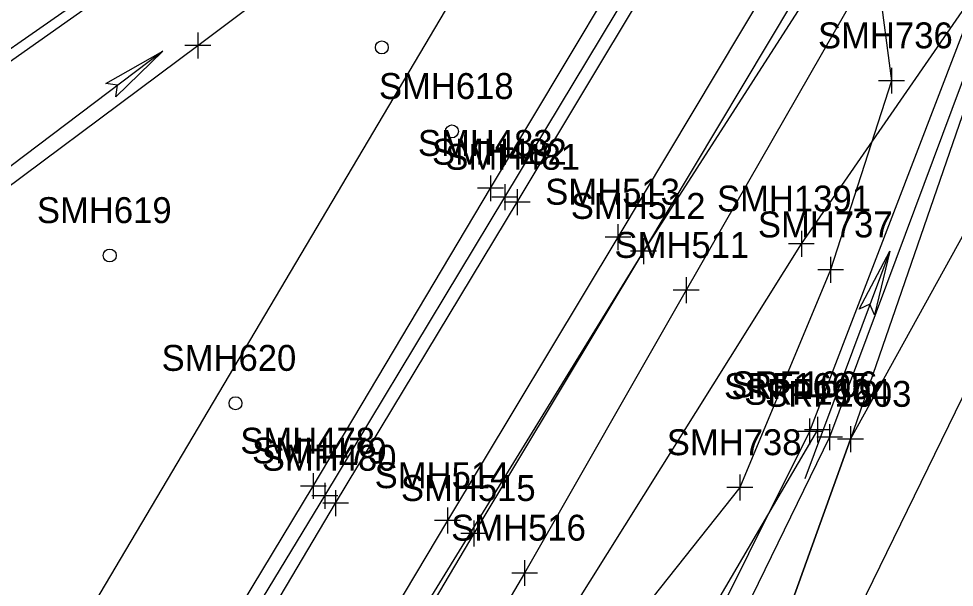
# Model space of a CAD drawing. Extents: x 941041 to 969446, y 397014 to 416764.
# Drawn here: x 952192.2 to 952336.7, y 403311.8 to 403399.5 of the extents above; entities that cross this region are included whole.
import ezdxf

# ---------------------------------------------------------------- set-up
doc = ezdxf.new("R2010")
doc.units = 0
for name, color, linetype in [('SURVEY - DRAINAGE - Area Shapes', 7, 'Continuous'), ('SURVEY - DRAINAGE - Area Shapes Text', 7, 'Continuous'), ('SURVEY - DTM - Breaklines', 7, 'Continuous'), ('SURVEY - DTM - Breaklines - Points - Locators', 7, 'Continuous'), ('SURVEY - DTM - Breaklines - Points - Numbers', 7, 'Continuous'), ('SURVEY - DTM - Spot Points - Locators', 7, 'Continuous'), ('SURVEY - DTM - Spot Points - Point Numbers', 7, 'Continuous'), ('SURVEY - DTM GRAPHICS - Boundary Line', 7, 'Continuous'), ('SURVEY - NON-TRANSPORTATION - Features', 7, 'Continuous'), ('SURVEY - NON-TRANSPORTATION - Features - Points - Locators', 7, 'Continuous'), ('SURVEY - NON-TRANSPORTATION - Features - Points - Numbers', 7, 'Continuous'), ('SURVEY - TRANSPORTATION - Features', 7, 'Continuous'), ('SURVEY - TRANSPORTATION - Features - Points - Locators', 7, 'Continuous'), ('SURVEY - TRANSPORTATION - Features - Points - Numbers', 7, 'Continuous'), ('SURVEY - TRANSPORTATION - Roads', 7, 'Continuous'), ('SURVEY - TRANSPORTATION - Roads - Points - Locators', 7, 'Continuous'), ('SURVEY - TRANSPORTATION - Roads - Points - Numbers', 7, 'Continuous'), ('SURVEY - VEGETATION - Features - Points - Locators', 7, 'Continuous'), ('SURVEY - VEGETATION - Features - Points - Numbers', 7, 'Continuous'), ('SURVEY - VEGETATION - Features with Text', 7, 'Continuous')]:
    doc.layers.add(name, color=color, linetype=linetype)

msp = doc.modelspace()

# ---------------------------------------------------------------- linework, layer by layer
at = {"layer": 'SURVEY - DRAINAGE - Area Shapes'}
msp.add_lwpolyline([(952524.78, 403657.05), (952492.12, 403619.04), (952377.47, 403501.88), (952288.71, 403363.65), (952144.73, 403130.14), (952066.04, 403042.14), (951972.88, 402968.67), (951909.7, 402961.24), (951854.04, 402976.32), (951847.06, 402862.63), (951840.23, 402758.71), (951891.23, 402760.8), (952228.34, 402790.58), (952361.3, 402834.13), (953526.16, 402149.04), (954070.26, 402059.9)], dxfattribs=at)
at = {"layer": 'SURVEY - DRAINAGE - Area Shapes Text'}
for p, q in [((952214.42, 403394.56), (952184.5, 403371.92)), ((952326.74, 403363.69), (952313.64, 403328.54))]:
    msp.add_line(p, q, dxfattribs=at)
for points in [[(952214.42, 403394.56), (952207.16, 403387.49), (952207.44, 403389.28), (952205.62, 403389.53)], [(952326.74, 403363.69), (952324.4, 403353.84), (952323.69, 403355.49), (952322.01, 403354.73)]]:
    msp.add_lwpolyline(points, close=True, dxfattribs=at)
for points in [[(952214.42, 403394.56), (952207.16, 403387.49), (952207.44, 403389.28), (952205.62, 403389.53), (952214.42, 403394.56)], [(952326.74, 403363.69), (952324.4, 403353.84), (952323.69, 403355.49), (952322.01, 403354.73), (952326.74, 403363.69)]]:
    msp.add_lwpolyline(points, dxfattribs=at)
at = {"layer": 'SURVEY - DTM - Breaklines'}
for points in [[(952736.12, 403724.5), (952691.91, 403690.39), (952652.91, 403661.72), (952597.79, 403620.04), (952558.5, 403596.43), (952540.39, 403606.94), (952539.83, 403606.39), (952554.53, 403592.08), (952552.67, 403578.76), (952522.24, 403557.97), (952459.92, 403516.62), (952405.87, 403481.47), (952366.05, 403438.15), (952349.58, 403421.1), (952343.82, 403412.52), (952314.34, 403335.84)], [(952737.07, 403722.49), (952692.53, 403689.24), (952653.03, 403660.5), (952601.74, 403618.14), (952557.82, 403590.87), (952555.49, 403578.9), (952523.84, 403556.42), (952459.22, 403512.77), (952406.44, 403479.97), (952366.72, 403437.08), (952351.28, 403418.78), (952351.07, 403418.51), (952346.58, 403413.01), (952317.46, 403334.95)], [(952745.6, 403709.26), (952701.3, 403681.67), (952659.46, 403650.99), (952608.65, 403618.13), (952559.91, 403588.24), (952555.32, 403575.05), (952528.03, 403556.34), (952406.89, 403478.52), (952352.92, 403416.94), (952346.34, 403408.88), (952320.69, 403334.64)], [(952450.65, 403522.86), (952407.71, 403486.54), (952386.56, 403463.73), (952361.86, 403438.59), (952338.46, 403412.93), (952329.89, 403411.67), (952325, 403405.24), (952327.02, 403389.98), (952317.62, 403360.79), (952303.59, 403327.17), (952284.04, 403302.52), (952269.86, 403290.27), (952268.05, 403273.15), (952243.67, 403236.98), (952228.06, 403211.3)], [(952284.32, 403445.19), (952160.86, 403236.96), (952125.87, 403192.45), (952077.94, 403136.62), (952039.19, 403098.25), (952006.25, 403068.24), (951969.46, 403038.09), (951934.26, 403008.18), (951912.19, 402997.34), (951900.8, 403002.03), (951909.31, 403040.46), (951919.74, 403082.57), (951927.08, 403105.04), (951926.24, 403141.28), (951910.03, 403171.31), (951930.4, 403184.14)], [(951846.56, 403146.1), (951882.59, 403170.26), (951887.03, 403170.6), (951935.22, 403196.94), (951981.81, 403226.14), (952031.67, 403259.48), (952078.26, 403295.42), (952132.19, 403332.31), (952180.72, 403366.29), (952219.86, 403395.41), (952263.53, 403428.2), (952276.96, 403440.29)], [(952314.34, 403335.84), (952295.48, 403298.04), (952287.97, 403297.72), (952283.48, 403298.01), (952280.8, 403296.79), (952277.5, 403290.62), (952277, 403283.29), (952275.15, 403274.98), (952251.42, 403239.31), (952241.82, 403231.73), (952239.1, 403218.29), (952233.04, 403217.68), (952229.48, 403212.47), (952228.21, 403209.66)], [(952320.69, 403334.64), (952305.43, 403292.27), (952302.37, 403268.11), (952296.52, 403262.95), (952290.35, 403264.85), (952288.43, 403272.15), (952287.03, 403287.42), (952283.61, 403276.26), (952277.71, 403262.68), (952259.83, 403237.91), (952232.37, 403203.9), (952228.62, 403205.38), (952226.63, 403209.28)], [(952317.46, 403334.95), (952298.46, 403295.99), (952294.47, 403284.98), (952295.57, 403281.12), (952299.28, 403276.61), (952295.68, 403264.4), (952293.7, 403264.45), (952291.51, 403276.3), (952292.83, 403291.39), (952287.44, 403296.11), (952283.91, 403296.92), (952280.85, 403295.58), (952279.54, 403292.12), (952279.18, 403285.26), (952277.21, 403274.17), (952254.29, 403239.28), (952242.97, 403231.14), (952241.09, 403217.51), (952237.16, 403215.54), (952233.62, 403215.55), (952231.5, 403211.94), (952231.07, 403206.38)]]:
    msp.add_lwpolyline(points, dxfattribs=at)
at = {"layer": 'SURVEY - DTM - Breaklines - Points - Locators'}
for p, q in [((952219.86, 403397.41), (952219.86, 403393.41)), ((952221.86, 403395.41), (952217.86, 403395.41)), ((952327.02, 403391.98), (952327.02, 403387.98)), ((952329.02, 403389.98), (952325.02, 403389.98)), ((952317.62, 403362.79), (952317.62, 403358.79)), ((952319.62, 403360.79), (952315.62, 403360.79)), ((952314.34, 403337.84), (952314.34, 403333.84)), ((952316.34, 403335.84), (952312.34, 403335.84)), ((952317.46, 403336.95), (952317.46, 403332.95)), ((952320.69, 403336.64), (952320.69, 403332.64)), ((952319.46, 403334.95), (952315.46, 403334.95)), ((952322.69, 403334.64), (952318.69, 403334.64)), ((952303.59, 403329.17), (952303.59, 403325.17)), ((952305.59, 403327.17), (952301.59, 403327.17))]:
    msp.add_line(p, q, dxfattribs=at)
at = {"layer": 'SURVEY - DTM - Spot Points - Locators'}
for centre in [(952248.28, 403395.12), (952259.11, 403382.16), (952206.24, 403363), (952225.67, 403340.19)]:
    msp.add_circle(centre, 1, dxfattribs=at)
at = {"layer": 'SURVEY - DTM GRAPHICS - Boundary Line'}
msp.add_lwpolyline([(952035.48, 402957.27), (952071.58, 402994.93), (952104.2, 403029.37), (952152.09, 403078.34), (952185.06, 403125.25), (952207.21, 403161.01), (952229.39, 403196.73), (952259.83, 403237.91), (952277.71, 403262.68), (952290.35, 403264.85), (952296.52, 403262.95), (952302.37, 403268.11), (952305.43, 403292.27), (952320.69, 403334.64), (952358.07, 403402.28), (952434.4, 403461.68), (952438.94, 403466.81), (952457.13, 403479.78), (952544.24, 403540.36), (952613.11, 403589.47), (952670.27, 403628.77)], dxfattribs=at)
at = {"layer": 'SURVEY - NON-TRANSPORTATION - Features'}
msp.add_lwpolyline([(952315.59, 403336.11), (952294.52, 403300.16), (952254.66, 403237.53), (952229.39, 403196.73), (952207.21, 403161.01), (952185.06, 403125.25), (952152.09, 403078.34), (952104.2, 403029.37), (952071.58, 402994.93), (952035.48, 402957.27), (951996.22, 402916.22), (951962.85, 402881.47), (951907.47, 402820.96)], dxfattribs=at)
at = {"layer": 'SURVEY - NON-TRANSPORTATION - Features - Points - Locators'}
for p, q in [((952315.59, 403338.11), (952315.59, 403334.11)), ((952317.59, 403336.11), (952313.59, 403336.11))]:
    msp.add_line(p, q, dxfattribs=at)
at = {"layer": 'SURVEY - TRANSPORTATION - Features'}
for points in [[(952463.7, 403566.84), (952424.44, 403532.16), (952386.95, 403493.43), (952352.93, 403451.33), (952321.99, 403404.14), (952295.3, 403357.63), (952270.34, 403313.98), (952241.93, 403265.74), (952208.83, 403217.23), (952179.84, 403174.88), (952146.26, 403127.61), (952109.6, 403083.06), (952068.28, 403040.45), (952026.52, 403003), (951981.94, 402968.99), (951929.76, 402929.79), (951899.74, 402893.98), (951883.92, 402865.94), (951878.37, 402845.72), (951874.04, 402827.93), (951876.74, 402809.53), (951887.15, 402791.78)], [(952356.31, 403508.85), (952319.54, 403482.53), (952271.2, 403449.46), (952218.02, 403412.1), (952168.51, 403377.19), (952118.64, 403342.5), (952070.41, 403308.53), (952018.6, 403272.33), (951969.85, 403238.11), (951920.07, 403203.33), (951882.16, 403176.11), (951845.47, 403150.79)], [(951876.39, 403112.43), (951877.41, 403108.88), (951874.65, 403046.53), (951875.12, 403005.5), (951885.48, 402985.02), (951901.34, 402976.24), (951925.41, 402975.64), (951956.41, 402989.5), (952002.91, 403023.51), (952035.36, 403050.69), (952073.7, 403089.73), (952112.45, 403134.55), (952147.27, 403180.21), (952178.93, 403228.56), (952206.23, 403275.42), (952237.69, 403327.41), (952265.08, 403373.37), (952295.28, 403423.85), (952326.86, 403470.47), (952353.56, 403504.36)]]:
    msp.add_lwpolyline(points, dxfattribs=at)
at = {"layer": 'SURVEY - TRANSPORTATION - Features - Points - Locators'}
for p, q in [((952265.08, 403375.37), (952265.08, 403371.37)), ((952267.08, 403373.37), (952263.08, 403373.37)), ((952295.3, 403359.63), (952295.3, 403355.63)), ((952297.3, 403357.63), (952293.3, 403357.63)), ((952237.69, 403329.41), (952237.69, 403325.41)), ((952239.69, 403327.41), (952235.69, 403327.41)), ((952270.34, 403315.98), (952270.34, 403311.98)), ((952272.34, 403313.98), (952268.34, 403313.98))]:
    msp.add_line(p, q, dxfattribs=at)
at = {"layer": 'SURVEY - TRANSPORTATION - Roads'}
for points in [[(951865.8, 403008.31), (951866.15, 403005.56), (951870.88, 402986.54), (951882.98, 402972.26), (951909.7, 402961.24), (951937.83, 402969.25), (951963.44, 402985.92), (951994.04, 403009.28), (952032.28, 403040.88), (952076.34, 403084), (952116.65, 403130.24), (952151.69, 403177.54), (952182.07, 403225.35), (952210.54, 403273.2), (952241.14, 403324.77), (952269.17, 403371.23), (952298.83, 403420.63), (952331.01, 403468.12), (952356.67, 403501.3), (952395.48, 403543.21), (952445.2, 403585.68)], [(952455.35, 403576.86), (952415.67, 403541.68), (952377.47, 403501.88), (952343.29, 403458.44), (952311.51, 403410.58), (952284.76, 403365.84), (952258.41, 403322.08), (952230.37, 403275.05), (952199.68, 403223.63), (952172.53, 403180.11), (952139.24, 403133), (952102.73, 403089.01), (952061.21, 403046.18), (952018.15, 403007.86), (951970.15, 402971.5), (951933.15, 402944.53), (951910.93, 402922.73), (951891.55, 402898.16), (951877.55, 402875.89), (951859.36, 402837.53)], [(952459.67, 403571.86), (952420.1, 403537.84), (952381.8, 403498.21), (952347.63, 403456.07), (952315.62, 403408.68), (952288.71, 403363.65), (952262.47, 403320.1), (952234.46, 403272.79), (952203.33, 403221.24), (952176.72, 403177.53), (952143.38, 403130.61), (952105.84, 403085.28), (952064.68, 403043.34), (952020.29, 403004.45), (951972.88, 402968.67), (951935.5, 402941.59), (951914.66, 402920.84), (951894.55, 402896.1), (951881.05, 402875.02), (951865.64, 402835.43)], [(952363.66, 403516.11), (952318.6, 403484.64), (952270.5, 403450.6), (952217.03, 403413.11), (952165.82, 403377.48), (952117.66, 403343.68), (952069.64, 403309.92), (952017.59, 403273.34), (951968.61, 403239.23), (951919.39, 403204.95), (951881.03, 403178.29), (951848.45, 403157.23)], [(951868.66, 403020.4), (951868.75, 403005.58), (951874.6, 402988.78), (951885.58, 402976.09), (951909.34, 402966.72), (951936.24, 402972.08), (951962.8, 402986.78), (951993.75, 403010.02), (952030.85, 403042.24), (952075.7, 403086.1), (952114.61, 403131.25), (952149.56, 403178.29), (952180.65, 403227.07), (952208.11, 403274.26), (952239.48, 403325.89), (952267.27, 403372.02), (952297.15, 403421.58), (952329.18, 403469.36), (952355.05, 403502.68), (952364.99, 403515.15)]]:
    msp.add_lwpolyline(points, dxfattribs=at)
at = {"layer": 'SURVEY - TRANSPORTATION - Roads - Points - Locators'}
for p, q in [((952267.27, 403374.02), (952267.27, 403370.02)), ((952269.17, 403373.23), (952269.17, 403369.23)), ((952269.27, 403372.02), (952265.27, 403372.02)), ((952271.17, 403371.23), (952267.17, 403371.23)), ((952284.76, 403367.84), (952284.76, 403363.84)), ((952286.76, 403365.84), (952282.76, 403365.84)), ((952288.71, 403365.65), (952288.71, 403361.65)), ((952288.71, 403365.65), (952288.71, 403361.65)), ((952290.71, 403363.65), (952286.71, 403363.65)), ((952290.71, 403363.65), (952286.71, 403363.65)), ((952239.48, 403327.89), (952239.48, 403323.89)), ((952241.48, 403325.89), (952237.48, 403325.89)), ((952241.14, 403326.77), (952241.14, 403322.77)), ((952243.14, 403324.77), (952239.14, 403324.77)), ((952258.41, 403324.08), (952258.41, 403320.08)), ((952260.41, 403322.08), (952256.41, 403322.08)), ((952262.47, 403322.1), (952262.47, 403318.1)), ((952264.47, 403320.1), (952260.47, 403320.1))]:
    msp.add_line(p, q, dxfattribs=at)
at = {"layer": 'SURVEY - VEGETATION - Features - Points - Locators'}
for p, q in [((952313.09, 403366.79), (952313.09, 403362.79)), ((952315.09, 403364.79), (952311.09, 403364.79))]:
    msp.add_line(p, q, dxfattribs=at)
at = {"layer": 'SURVEY - VEGETATION - Features with Text'}
msp.add_lwpolyline([(953978, 404545.36), (952376.77, 403420.76), (952302.37, 403268.11), (952235, 403233.08), (952263.4, 403271.68), (952268, 403292.82), (952313.09, 403364.79), (952374.61, 403453.68), (952430.54, 403509.23), (952518.9, 403556.35), (952567.29, 403603.14), (952615.41, 403645.7), (952663.71, 403647.1)], dxfattribs=at)

# ---------------------------------------------------------------- texts
at = {"layer": 'SURVEY - DTM - Breaklines - Points - Numbers'}
for s, p in [('SMH736', (952315.67, 403394.98)), ('SMH737', (952306.38, 403365.79)), ('SRF1605', (952301.15, 403340.84)), ('SRF1604', (952304.26, 403339.95)), ('SRF1603', (952307.5, 403339.64)), ('SMH738', (952292.3, 403332.17))]:
    msp.add_text(s, height=4, dxfattribs=at).set_placement(p)
at = {"layer": 'SURVEY - DTM - Spot Points - Point Numbers'}
for s, p in [('SMH618', (952247.83, 403387.16)), ('SMH619', (952194.99, 403368)), ('SMH620', (952214.25, 403345.19))]:
    msp.add_text(s, height=4, dxfattribs=at).set_placement(p)
at = {"layer": 'SURVEY - NON-TRANSPORTATION - Features - Points - Numbers'}
msp.add_text('SRF1606', height=4, dxfattribs=at).set_placement((952302.28, 403341.11))
at = {"layer": 'SURVEY - TRANSPORTATION - Features - Points - Numbers'}
for s, p in [('SMH483', (952253.85, 403378.37)), ('SMH511', (952284.22, 403362.63)), ('SMH478', (952226.41, 403332.41)), ('SMH516', (952258.99, 403318.98))]:
    msp.add_text(s, height=4, dxfattribs=at).set_placement(p)
at = {"layer": 'SURVEY - TRANSPORTATION - Roads - Points - Numbers'}
for s, p in [('SMH482', (952256.03, 403377.02)), ('SMH481', (952258.09, 403376.23)), ('SMH513', (952273.52, 403370.84)), ('SMH512', (952277.47, 403368.65)), ('SMH512', (952277.47, 403368.65)), ('SMH479', (952228.23, 403330.89)), ('SMH480', (952229.73, 403329.77)), ('SMH514', (952247.17, 403327.08)), ('SMH515', (952251.23, 403325.1))]:
    msp.add_text(s, height=4, dxfattribs=at).set_placement(p)
at = {"layer": 'SURVEY - VEGETATION - Features - Points - Numbers'}
msp.add_text('SMH1391', height=4, dxfattribs=at).set_placement((952300.06, 403369.79))

doc.saveas('drawing.dxf')
